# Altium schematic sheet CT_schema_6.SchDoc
size 368 x 333 mm
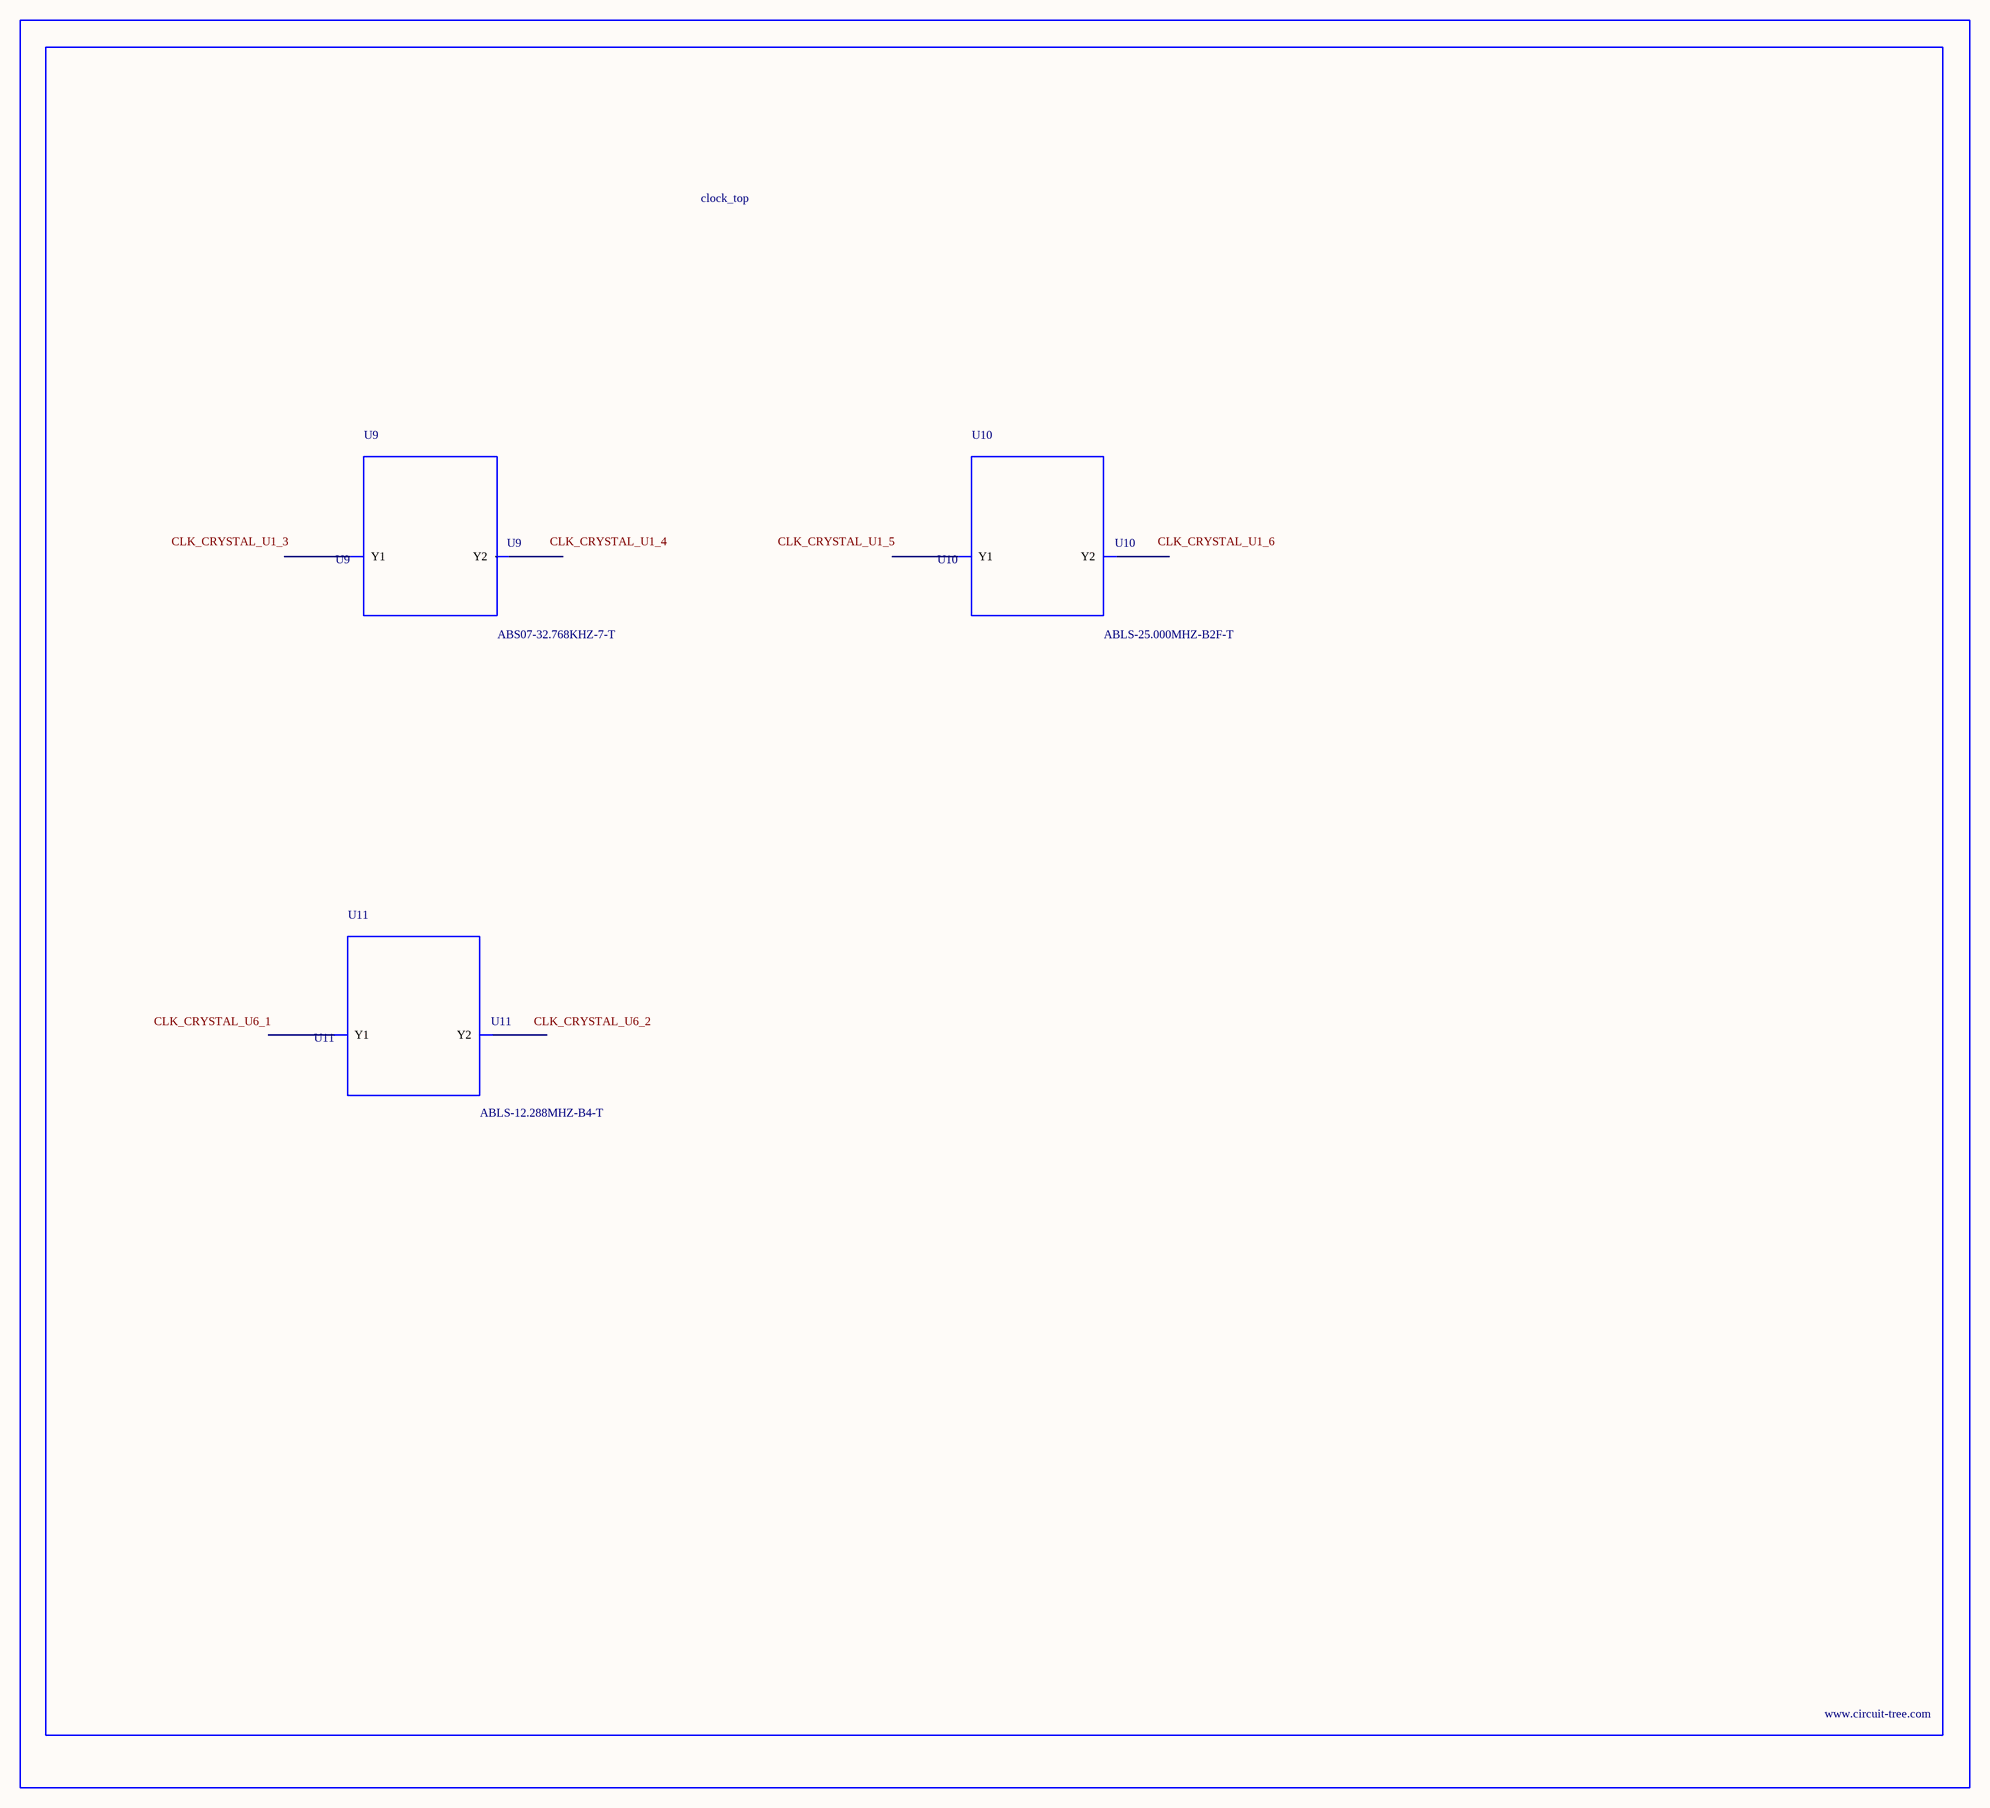
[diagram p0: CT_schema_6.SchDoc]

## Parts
BORDER5  (no value)
U9  ABS07-32.768KHZ-7-T  [ABS07-32.768KHZ-7-T]
U10  ABLS-25.000MHZ-B2F-T  [ABLS-25.000MHZ-B2F-T]
U11  ABLS-12.288MHZ-B4-T  [ABLS-12.288MHZ-B4-T]

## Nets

Not connected (* = marked no-connect by the designer): U9 1(Y1) 2(Y2); U10 1(Y1) 2(Y2); U11 1(Y1) 2(Y2)

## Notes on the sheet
- Labels drawn without touching a wire or pin: CLK_CRYSTAL_U1_3, CLK_CRYSTAL_U1_4, CLK_CRYSTAL_U1_5, CLK_CRYSTAL_U1_6, CLK_CRYSTAL_U6_1, CLK_CRYSTAL_U6_2

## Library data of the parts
BORDER5 = BORDER_PAGE5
